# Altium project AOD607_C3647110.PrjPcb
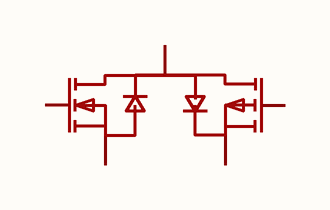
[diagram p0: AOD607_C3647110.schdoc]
1 sheet, 1 parts. Net scope: global (net labels, ports and power ports of the same name join across sheets).

## Sheet AOD607_C3647110.schdoc
size 127 x 101 mm

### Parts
Q?  aod607-ms  [TO-252-4_L6.6-W6.1-P1.27-LS10-TL]  (value not drawn)

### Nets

Not connected (* = marked no-connect by the designer): Q? 1(S) 2(G) 3(D) 4(S) 5(G)

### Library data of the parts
Q? = aod607-ms: 数量:1个N沟道+1个P沟道;漏源电压(Vdss):30V;连续漏极电流(Id):16A;导通电阻(RDS(on)):68mΩ@4.5V;耗散功率(Pd):32.5W;阈值电压(Vgs(th)):2.5V;; Manufacturer: MSKSEMI(美森科); Symbol: AOD607_C3647110; AddInBom: yes; ModelId: 8151d6e4b177452b8925147fa9fba861; ModelTransform: 259.99948,389.763,0,270,0,0,28.464,-0.001,0; Drain to Source Voltage: 30V; Current - Continuous Drain(Id): 16A; Pd - Power Dissipation: 32.5W; Gate Threshold Voltage (Vgs(th)): 2.5V; Gate Charge(Qg): 8nC@4.5V; Input Capacitance(Ciss): 620pF; Configuration: 半桥；全桥; Type: N沟道+P沟道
